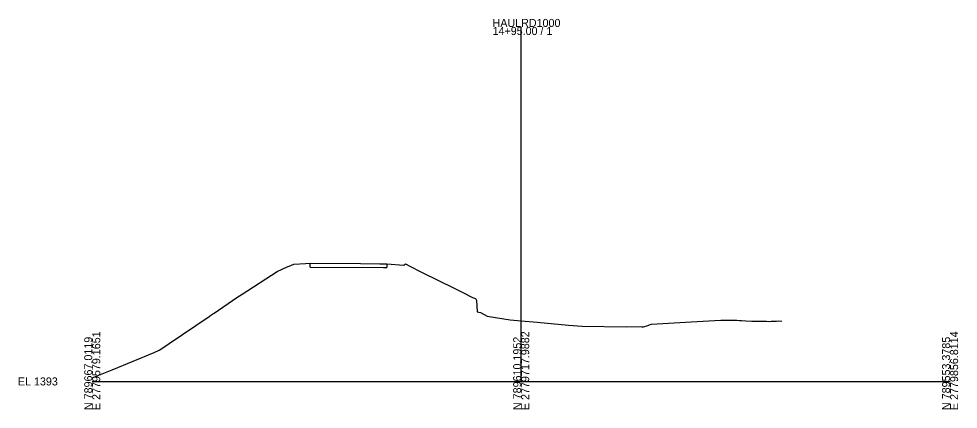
# Model space of a CAD drawing. Extents: x -5952 to 1603, y -4765 to 11607.
# Drawn here: x 1274.3 to 1602.8, y 490.3 to 626.6 of the extents above; entities that cross this region are included whole.
import ezdxf

# ---------------------------------------------------------------- set-up
doc = ezdxf.new("R2010")
doc.units = 0
for name, color, linetype in [('DESIGN - SHEET - Light Grid', 7, 'Continuous'), ('SURVEY - GROUND - Existing Pavement Layer', 7, 'Continuous'), ('SURVEY - GROUND - Top of Ground', 7, 'Continuous')]:
    doc.layers.add(name, color=color, linetype=linetype)

msp = doc.modelspace()

# ---------------------------------------------------------------- linework, layer by layer
at = {"layer": 'DESIGN - SHEET - Light Grid'}
for p, q in [((1450, 500), (1450, 623.78)), ((1300, 500), (1450, 500)), ((1450, 500), (1600, 500))]:
    msp.add_line(p, q, dxfattribs=at)
at = {"layer": 'SURVEY - GROUND - Existing Pavement Layer'}
for p, q in [((1376.24, 539.93), (1376.24, 541.26)), ((1376.24, 539.93), (1401.84, 539.78)), ((1401.84, 539.78), (1402.99, 539.77)), ((1402.99, 541.07), (1402.99, 539.77))]:
    msp.add_line(p, q, dxfattribs=at)
at = {"layer": 'SURVEY - GROUND - Top of Ground'}
msp.add_lwpolyline([(1300, 501.27), (1304.09, 502.88), (1307.01, 504.05), (1321.65, 510.14), (1323.44, 510.95), (1324.34, 511.54), (1326.94, 513.29), (1340.92, 522.71), (1341.5, 523.14), (1342.18, 523.6), (1342.61, 523.79), (1350.56, 529.33), (1352.45, 530.47), (1364.72, 538.33), (1368.17, 540.01), (1368.91, 540.27), (1370.46, 540.95), (1374.57, 541.17), (1376.24, 541.26), (1393.78, 541.15), (1400.61, 541.09), (1402.36, 541.09), (1402.99, 541.07), (1408.97, 540.62), (1409.6, 541.05), (1411.11, 540.3), (1415.12, 538.15), (1426.8, 532.44), (1429.61, 531.07), (1432.93, 529.28), (1434.06, 528.96), (1434.35, 528.25), (1434.62, 524.27), (1435.82, 524.09), (1438.07, 522.81), (1446.11, 521.55), (1450, 521.19), (1455.62, 520.66), (1466.5, 519.69), (1471.29, 519.32), (1486.81, 519.06), (1492.19, 519.18), (1492.42, 518.94), (1494.7, 519.59), (1494.74, 519.74), (1495.53, 519.98), (1509.45, 520.84), (1519.78, 521.4), (1520.13, 521.39), (1520.66, 521.39), (1521.46, 521.38), (1524.78, 521.35), (1525.43, 521.34), (1526.39, 521.33), (1527.03, 521.32), (1528.55, 521.11), (1530.66, 521.04), (1530.98, 521.02), (1532.6, 521.03), (1533.47, 521.03), (1534.5, 521.04), (1535.75, 521.05), (1536.85, 520.96), (1537.39, 521.01), (1538.37, 521.1), (1539.35, 521.1), (1539.83, 521.13), (1541.21, 521.07)], dxfattribs=at)

# ---------------------------------------------------------------- texts
at = {"layer": 'DESIGN - SHEET - Light Grid'}
for s, p in [('HAULRD1000', (1440, 623.78)), ('14+95.00 / 1', (1440, 620.98)), ('EL 1393', (1274, 498.6))]:
    msp.add_text(s, height=2.8, dxfattribs=at).set_placement(p)
for s, p in [('E 2779579.1651', (1302.8, 490)), ('E 2779717.9882', (1452.8, 490)), ('E 2779856.8114', (1602.8, 490)), ('N 789667.0119', (1300, 490)), ('N 789610.1952', (1450, 490)), ('N 789553.3785', (1600, 490))]:
    msp.add_text(s, height=2.8, rotation=90, dxfattribs=at).set_placement(p)

doc.saveas('drawing.dxf')
